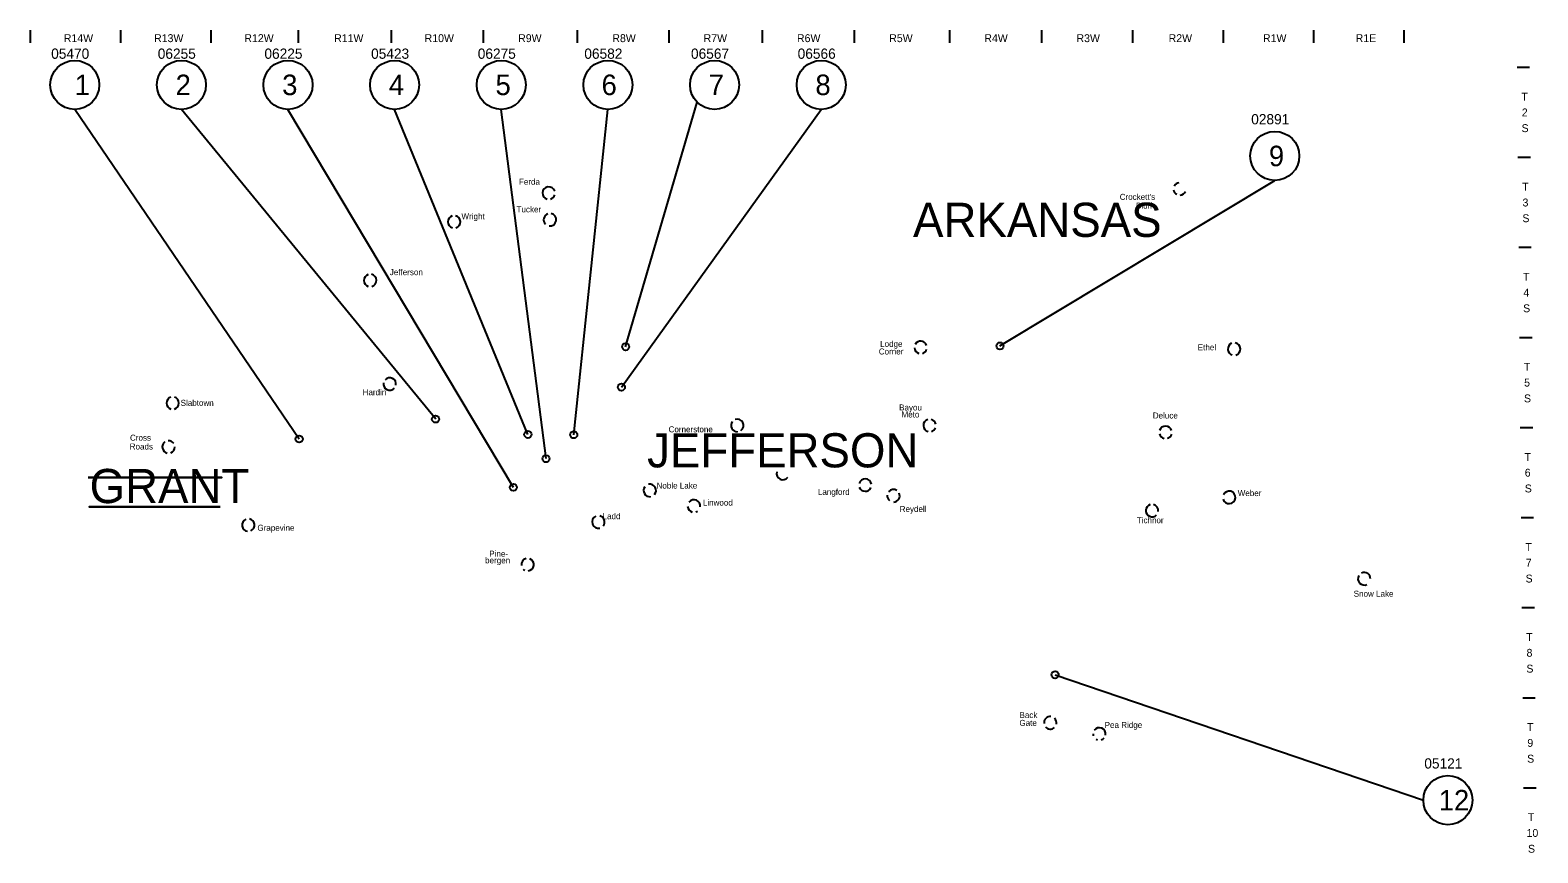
# Model space of a CAD drawing. Extents: x 3046 to 131673, y -8885 to 10756.
# Drawn here: x 34666 to 52320, y 1123 to 10749 of the extents above; entities that cross this region are included whole.
import ezdxf

# ---------------------------------------------------------------- set-up
doc = ezdxf.new("R2010")
doc.units = 0
for name, color, linetype in [('2', 7, 'Continuous'), ('Default', 7, 'Continuous'), ('Level 24', 7, 'Continuous'), ('R_Annotation', 7, 'Continuous'), ('R_No Plot', 7, 'Continuous')]:
    doc.layers.add(name, color=color, linetype=linetype)

msp = doc.modelspace()

# ---------------------------------------------------------------- linework, layer by layer
at = {"layer": 'Default'}
for p, q in [((34666, 10749), (34666, 10602)), ((35723, 10749), (35723, 10602)), ((35723, 10749), (35723, 10602)), ((36780, 10749), (36780, 10602)), ((36780, 10749), (36780, 10602)), ((37805, 10749), (37805, 10602)), ((38895, 10749), (38895, 10602)), ((39971, 10749), (39971, 10602)), ((41073, 10749), (41073, 10602)), ((42143, 10749), (42143, 10602)), ((43238, 10749), (43238, 10602)), ((44316, 10749), (44316, 10602)), ((45430, 10749), (45430, 10602)), ((46509, 10749), (46509, 10602)), ((47573, 10749), (47573, 10602)), ((48636, 10749), (48636, 10602)), ((49693, 10749), (49693, 10602)), ((50750, 10749), (50750, 10602)), ((52224, 10312), (52078, 10312)), ((52234, 9258), (52087, 9258)), ((52243, 8204), (52097, 8204)), ((52252, 7150), (52106, 7150)), ((52262, 6096), (52115, 6096)), ((52271, 5042), (52125, 5042)), ((52281, 3988), (52134, 3988)), ((52290, 2934), (52144, 2934)), ((52299, 1880), (52153, 1880))]:
    msp.add_line(p, q, dxfattribs=at)
at = {"layer": 'Level 24'}
for centre, start, end in [((40738, 8842), 17.8547, 255.1032), ((48128, 8892), 187.5805, 240.8249), ((48128, 8892), 99.2598, 154.28), ((48128, 8892), 274.6627, 335.0921), ((40738, 8842), 286.6378, 344.5693), ((39630, 8507), 107.2556, 254.6873), ((39630, 8507), 286.3444, 75.5912), ((40752, 8531), 110.2472, 224.5438), ((40752, 8531), 263.5144, 78.1937), ((38647, 7821), 109.1829, 252.4086), ((38647, 7821), 285.4422, 77.3562), ((45093, 7037), 16.9672, 151.9025), ((48764, 7018), 114.0242, 251.9416), ((48764, 7018), 285.7613, 80.5544), ((45093, 7037), 184.638, 254.304), ((45093, 7037), 287.9458, 342.956), ((38877, 6608), 168.8477, 318.2301), ((38877, 6608), 351.1371, 136.7135), ((36335, 6385), 106.227, 253.5396), ((36335, 6385), 286.528, 73.5658), ((42946, 6124), 305.9951, 110.6589), ((45198, 6123), 106.7878, 257.1132), ((45198, 6123), 12.7861, 74.3434), ((42946, 6124), 142.6124, 273.3895), ((45198, 6123), 287.8087, 339.7082), ((47962, 6043), 194.8572, 255.6328), ((47962, 6043), 15.9401, 163.089), ((47962, 6043), 287.2861, 344.2868), ((36286, 5872), 124.4323, 258.9323), ((36286, 5872), 34.1187, 92.0426), ((36286, 5872), 291.8742, 0.1714), ((43479, 5562), 166.3898, 322.1705), ((44444, 5426), 9.6428, 165.295), ((41922, 5363), 144.5193, 275.9709), ((41922, 5363), 318.6764, 101.8137), ((44444, 5426), 198.7186, 337.5324), ((44775, 5301), 175.5952, 229.8655), ((44775, 5301), 55.8218, 141.2303), ((44775, 5301), 272.1476, 22.8646), ((48705, 5282), 195.1241, 155.1197), ((42438, 5181), 184.5336, 255.3399), ((42438, 5181), 351.2996, 141.4978), ((42438, 5181), 288.0186, 305.7968), ((47802, 5128), 107.4237, 316.8643), ((47802, 5128), 352.0989, 75.227), ((37220, 4958), 113.445, 264.2495), ((37220, 4958), 295.6556, 80.2614), ((41319, 4994), 112.5627, 284.9371), ((41319, 4994), 321.3831, 76.9167), ((40490, 4496), 102.3076, 189.7701), ((40490, 4496), 227.12, 244.0099), ((40490, 4496), 276.6574, 68.0346), ((50287, 4329), 147.5618, 296.4691), ((50287, 4329), 358.4983, 113.9842), ((46611, 2644), 84.4269, 187.3681), ((46611, 2644), 346.3451, 46.4809), ((46611, 2644), 219.6855, 313.678), ((47185, 2514), 177.8094, 196.2791), ((47185, 2514), 350.1747, 144.8277), ((47185, 2514), 239.3593, 252.5528), ((47185, 2514), 286.2476, 319.8366)]:
    msp.add_arc(centre, 73.3, start, end, dxfattribs=at)
at = {"layer": 'R_Annotation'}
for p, q in [((41639, 7044), (42478, 9906)), ((37816, 5965), (35188, 9822)), ((39415, 6198), (36437, 9822)), ((40324, 5399), (37685, 9822)), ((40494, 6018), (38934, 9822)), ((40707, 5735), (40183, 9822)), ((41031, 6015), (41432, 9822)), ((41589, 6572), (43929, 9822)), ((46022, 7054), (49240, 8990)), ((46667, 3206), (50981, 1739))]:
    msp.add_line(p, q, dxfattribs=at)
for points in [[(35347, 5516), (36911, 5516), (36911, 5516), (35347, 5516)], [(36889, 5172), (35358, 5172), (35358, 5172), (36889, 5172)]]:
    msp.add_lwpolyline(points, close=True, dxfattribs=at)
for centre, radius in [((35188, 10108), 287), ((36437, 10108), 287), ((37685, 10108), 287), ((38934, 10108), 287), ((40183, 10108), 287), ((41432, 10108), 287), ((42680, 10108), 287), ((43929, 10108), 287), ((49240, 9277), 287), ((41639, 7044), 41.7), ((46022, 7054), 41.7), ((41589, 6572), 41.7), ((39413, 6198), 41.7), ((37816, 5965), 41.7), ((40494, 6018), 41.7), ((41031, 6015), 41.7), ((40706, 5734), 41.7), ((40324, 5399), 41.7), ((46667, 3206), 41.7), ((51267, 1739), 287)]:
    msp.add_circle(centre, radius, dxfattribs=at)

# ---------------------------------------------------------------- texts
at = {"layer": '2'}
for s, height, p in [('R14W', 92.4, (35060, 10609)), ('R13W', 92.4, (36117, 10609)), ('R12W', 92.4, (37174, 10609)), ('R11W', 92.4, (38225, 10609)), ('R10W', 92.4, (39285, 10609)), ('R9W', 92.4, (40380, 10609)), ('R8W', 92.4, (41483, 10609)), ('R7W', 92.4, (42552, 10609)), ('R6W', 92.4, (43645, 10609)), ('R5W', 92.4, (44725, 10609)), ('R4W', 92.4, (45839, 10609)), ('R3W', 92.4, (46918, 10609)), ('R2W', 92.4, (47997, 10609)), ('R1W', 92.4, (49102, 10609)), ('R1E', 92.4, (50187, 10609)), ('T', 92.4, (52128, 9925)), ('2', 92.4, (52132, 9740)), ('S', 92.4, (52130, 9556)), ('T', 92.4, (52137, 8871)), ('ARKANSAS', 399.6, (45004, 8330)), ('3', 92.4, (52141, 8686)), ('S', 92.4, (52139, 8502)), ('T', 92.4, (52147, 7817)), ('4', 92.4, (52151, 7632)), ('S', 92.4, (52148, 7448)), ('T', 92.4, (52156, 6763)), ('5', 92.4, (52160, 6579)), ('S', 92.4, (52158, 6394)), ('JEFFERSON', 399.6, (41890, 5633)), ('T', 92.4, (52165, 5709)), ('GRANT', 399.6, (35362, 5215)), ('6', 92.4, (52167, 5525)), ('S', 92.4, (52167, 5340)), ('T', 92.4, (52175, 4656)), ('7', 92.4, (52179, 4471)), ('S', 92.4, (52177, 4286)), ('T', 92.4, (52184, 3602)), ('8', 92.4, (52188, 3417)), ('S', 92.4, (52186, 3232)), ('T', 92.4, (52194, 2548)), ('9', 92.4, (52197, 2363)), ('S', 92.4, (52195, 2178)), ('T', 92.4, (52203, 1494)), ('10', 92.4, (52188, 1309)), ('S', 92.4, (52205, 1124))]:
    msp.add_text(s, height=height, dxfattribs=at).set_placement(p)
at = {"layer": 'Level 24'}
for s, p in [('Ferda', (40389, 8940)), ("Crockett's", (47424, 8763)), ('Tucker', (40362, 8617)), ('Bluff', (47615, 8661)), ('Wright', (39716, 8536)), ('Jefferson', (38877, 7882)), ('Lodge ', (44619, 7043)), ('Ethel', (48338, 7003)), ('Corner', (44603, 6954)), ('Hardin', (38559, 6477)), ('Slabtown', (36428, 6353)), ('Bayou', (44841, 6299)), ('Meto', (44869, 6217)), ('Deluce', (47812, 6205)), ('Cross', (35835, 5945)), ('Cornerstone', (42142, 6043)), ('Roads', (35832, 5842)), ('Noble Lake', (42001, 5385)), ('Langford', (43890, 5311)), ('Weber', (48806, 5297)), ('Linwood', (42543, 5186)), ('Reydell', (44848, 5111)), ('Grapevine', (37327, 4891)), ('Ladd', (41369, 5027)), ('Tichnor', (47624, 4980)), ('Pine-', (40042, 4588)), ('bergen', (39993, 4510)), ('Snow Lake', (50164, 4120)), ('Gate', (46250, 2608)), ('Back', (46251, 2700)), ('Pea Ridge', (47248, 2584))]:
    msp.add_text(s, height=70.4, dxfattribs=at).set_placement(p)
at = {"layer": 'R_Annotation'}
for s, height, p in [('1', 240, (35188, 9989)), ('2', 240, (36369, 9989)), ('3', 240, (37617, 9989)), ('4', 240, (38866, 9989)), ('5', 240, (40115, 9989)), ('6', 240, (41357, 9989)), ('7', 240, (42612, 9989)), ('8', 240, (43861, 9989)), ('9', 240, (49171, 9157)), ('12', 239.8, (51160, 1619))]:
    msp.add_text(s, height=height, dxfattribs=at).set_placement(p)
at = {"layer": 'R_No Plot'}
for s, p in [('05470', (34912, 10414)), ('06255', (36160, 10414)), ('06225', (37409, 10414)), ('05423', (38658, 10414)), ('06275', (39907, 10414)), ('06582', (41155, 10414)), ('06567', (42404, 10414)), ('06566', (43653, 10414)), ('02891', (48964, 9647)), ('05121', (50991, 2109))]:
    msp.add_text(s, height=119.9, dxfattribs=at).set_placement(p)

doc.saveas('drawing.dxf')
